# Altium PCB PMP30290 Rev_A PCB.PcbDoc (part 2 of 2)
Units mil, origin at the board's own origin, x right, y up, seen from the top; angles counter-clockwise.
Board outline 2460 x 2050 mil, 4 copper layers (Top Layer, Inner Layer 1, Inner Layer 2, Bottom Layer), stack 84.834 mil thick; 95 components, 59 nets, 283 pads, 121 vias.
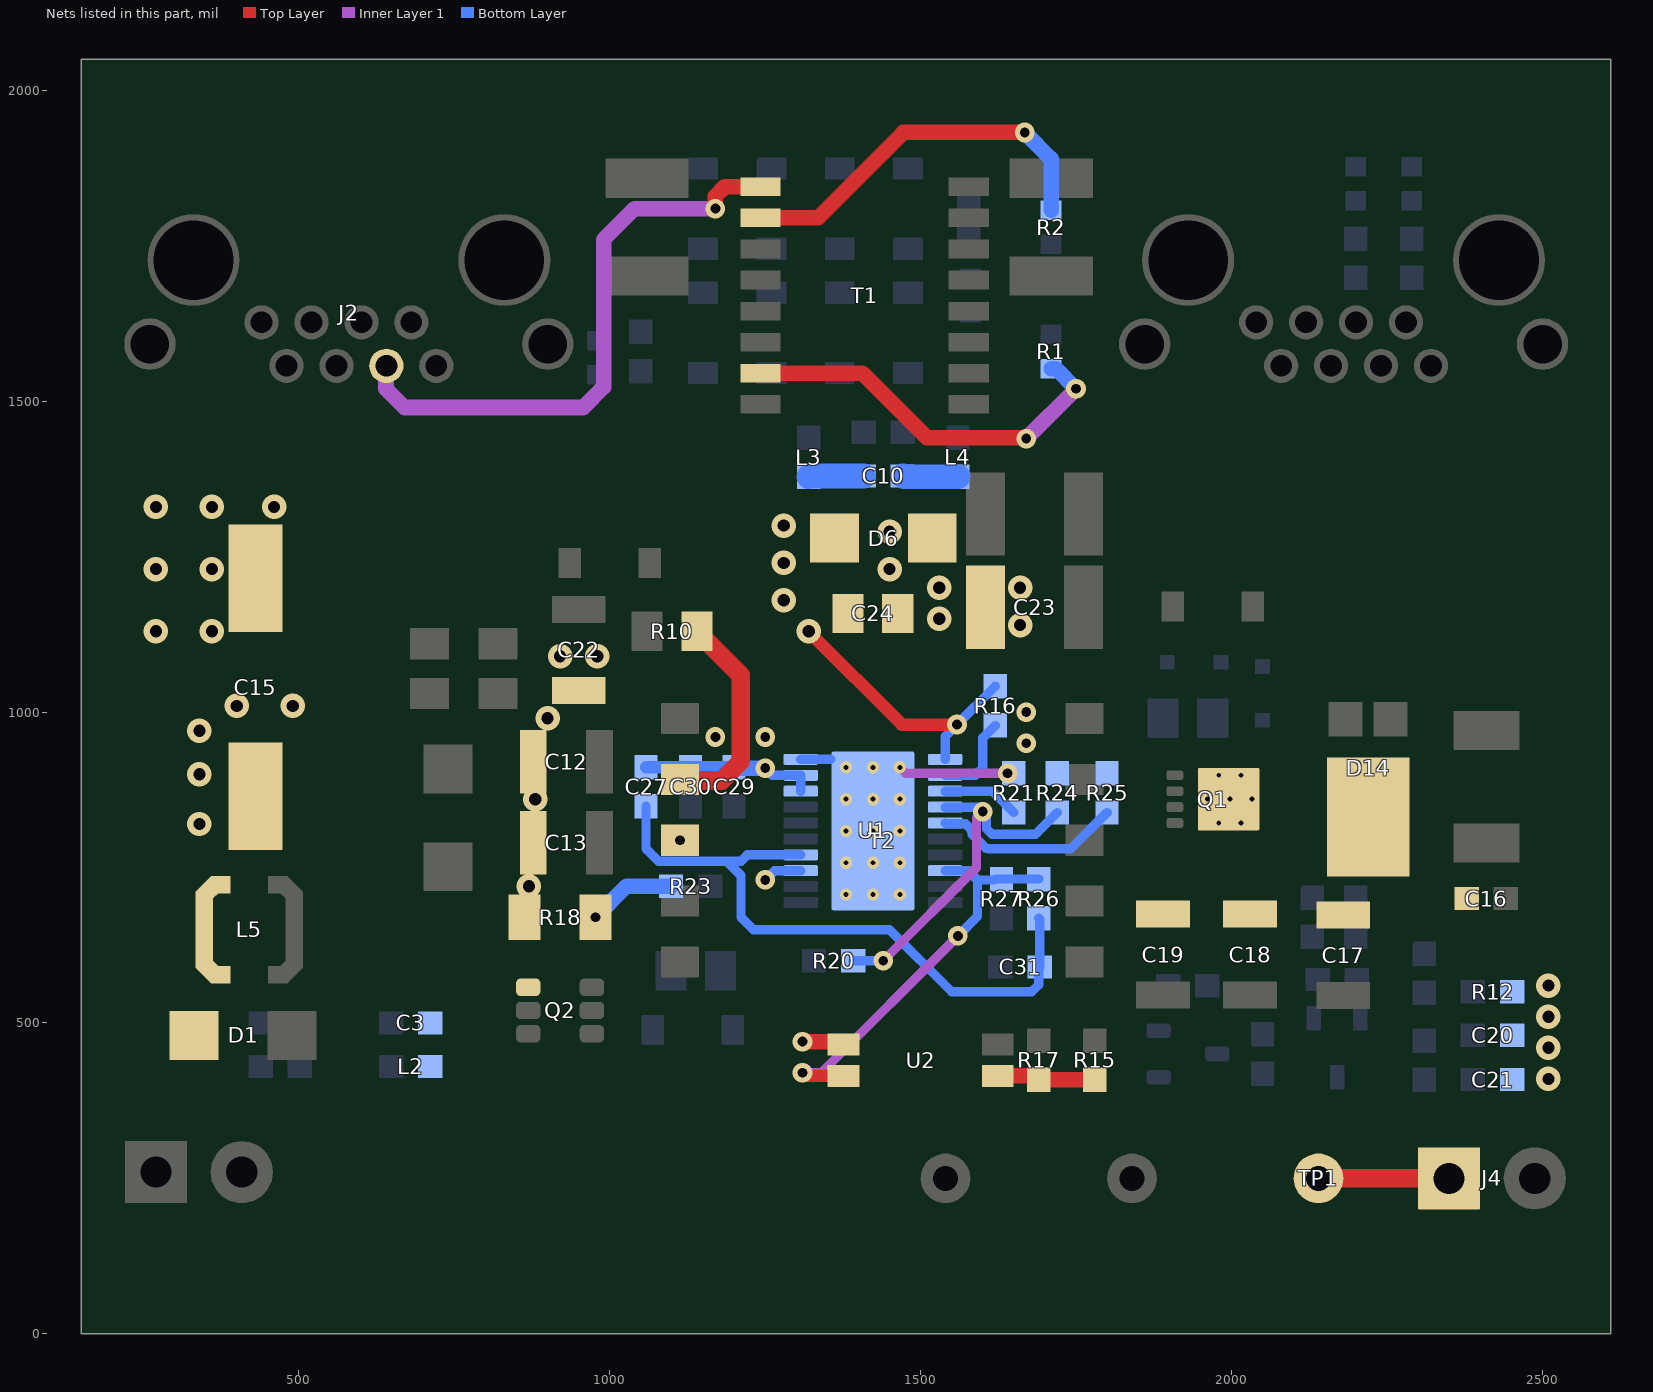
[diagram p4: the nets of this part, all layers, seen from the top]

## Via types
v1: diameter 39.37, hole 19.68, Top Layer to Bottom Layer, 53 vias
v2: diameter 31.5, hole 15.75, Top Layer to Bottom Layer, 46 vias
v3: diameter 19.68, hole 7.87, Top Layer to Bottom Layer, 16 vias
v4: diameter 19.68, hole 7.87, Top Layer to Bottom Layer, tented both sides, 6 vias

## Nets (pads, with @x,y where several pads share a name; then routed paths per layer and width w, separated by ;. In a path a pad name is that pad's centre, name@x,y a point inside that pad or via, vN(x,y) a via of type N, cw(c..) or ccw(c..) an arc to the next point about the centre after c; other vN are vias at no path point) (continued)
NetJ2_6: J2.6 T1.9 | length 949.9
  Top Layer w25: v2(1170,1810) 1170,1830 1185.01,1845.01 T1.9@1242.51,1845.01
  Inner Layer 1 w25: J2.6@640.63,1557.01 640,1556.38 640,1520 670,1490 957.24,1490 990,1522.76 990,1760 1040,1810 v2(1170,1810)
NetQ2_4: Q2.4 R18.2 R23.2 | length 142.1
  Bottom Layer w25: v2(977.09,670) 1027.09,720 R23.2@1098.5,720
NetR1_2: R1.2 T1.15 | length 637.6
  Top Layer w25: T1.15@1242.51,1545.01 1406.49,1545.01 1510,1441.5 1668.5,1441.5 v2(1670,1440)
  Inner Layer 1 w25: v2(1670,1440) v2(1750,1520)
  Bottom Layer w25: R1.2@1710,1552.44 1717.56,1552.44 v2(1750,1520)
NetR2_2: R2.2 T1.10 | length 624.4
  Top Layer w25: T1.10@1242.51,1795.01 1335.01,1795.01 1472.4,1932.4 v2(1667.6,1932.4)
  Bottom Layer w25: v2(1667.6,1932.4) 1710,1890 R2.2@1710,1807.56
NetR10_2: R10.2 T2.4 | length 349.9
  Top Layer w30: T2.4@1112.81,891.82 1114.63,890 1180,890 1210.61,920.61 1210.61,1059.39 R10.2@1140,1130
NetR15_1: R15.1 R17.2 U2.1 | length 158.7
  Top Layer w25: U2.1@1624.02,415 1683.5,415 R17.2@1690,408.5 R15.1@1780,408.5
NetR16_1: R16.1 U1.2 | length 142.2
  Bottom Layer w15: U1.2@1539.45,898.39 1588.39,898.39 1600,910 1600,958.5 R16.1@1620,978.5
NetR20_1: R20.1 R24.2 U1.4 | length 584.1
  Inner Layer 1 w15: v2(1440,600) 1590,750 1590,830 v2(1600,840)
  Bottom Layer w15: R20.1@1391.5,600 v2(1440,600) ; U1.4@1539.45,847.2 1598.72,847.2 1605.93,840 1605.93,812.45 1614.93,803.44 1684.94,803.44 R24.2@1720,838.5
NetR21_2: R21.2 U1.3 | length 124.8
  Bottom Layer w15: U1.3@1539.45,872.8 1615.71,872.8 R21.2@1650,838.5
NetR25_2: R25.2 U1.5 | length 305.8
  Bottom Layer w15: U1.5@1539.45,821.61 1540.81,820.26 1572.23,820.26 1582.38,810.11 1582.38,807.62 1583.05,806.95 1583.05,802.98 1605.46,780.57 1609.43,780.57 1610,780 1741.5,780 R25.2@1800,838.5
NetR26_1: R26.1 R27.1 U1.8 U2.4 | length 669.5
  Top Layer w20: v2(1310,420) 1315,415 U2.4@1375.98,415
  Inner Layer 1 w15: v2(1310,420) 1340,420 v2(1560,640)
  Bottom Layer w15: U1.8@1539.45,744.84 1576.61,744.84 1591.46,730 ; v2(1560,640) 1591.46,671.46 1591.46,730 ; R26.1@1690,731.5 1620,731.5 1618.5,730 1591.46,730
PWRGND: C3.2 C12.2 C13.2 C15.2 C22.2 C23.1 C27.1 C29.2 C30.2 L2.2 R18.1 R24.1 R25.1 T2.3 U1.13 U1.18 U1.19 U2.3 | length 411.2
  Top Layer w25: v2(1310,470) 1370.98,470 U2.3@1375.98,465
  Bottom Layer w15: v2(1250,730) 1264.84,744.84 U1.13@1307.17,744.84 ; v2(1250,910) 1261.61,898.39 U1.19@1307.17,898.39 U1.18@1307.17,872.8
  Bottom Layer w20: C27.1@1058.31,911.5 C30.2@1130,911.5 C29.2@1200,911.5
  Bottom Layer w25: C29.2@1200,911.5 1201.5,910 v2(1250,910)
  other v1: 870,720 880,860 900,990 920,1090 980,1090 270,1130 360,1130 1660,1140 1660,1200 270,1230 360,1230 270,1330 360,1330 460,1330
  other v2: 1112.81,793.82 1670,950 1170,960 1250,960 1670,1000
VB: C27.2 C31.1 R26.2 U1.14 | length 1070.3
  Bottom Layer w15: C27.2@1058.31,848.5 1058.31,780 1078.31,760 1190,760 ; U1.14@1307.17,770.43 1221.56,770.43 1211.12,760 1190,760 ; R26.2@1690,668.5 1691.5,667.01 C31.1@1691.5,590 1690,588.5 1690,561.46 1678.54,550 1550,550 1450,650 1231.12,650 1211.12,670 1211.12,737.06 1190,758.18 1190,760
VDD: C10.1 C15.1 C24.1 D1.1 D6.1 L3.2 L5.1 R16.2 U1.1 | length 540.6
  Top Layer w20: v1(1320,1130) 1470,980 v2(1558.5,980)
  Bottom Layer w15: U1.1@1539.45,923.98 1539.45,960.94 v2(1558.5,980) R16.2@1620,1041.5
  Bottom Layer w40: L3.2@1320,1378.5 1321.5,1380 C10.1@1408.5,1380
  other v1: 340,820 340,900 340,970 400,1010 490,1010 1280,1180 1280,1240 1280,1300
VOUT: C16.2 C17.1 C18.1 C19.1 C20.1 C21.1 D14.3 J4.1 Q1.5 Q1.6 Q1.7 Q1.8 Q1.9@1995.39,860 R12.2 TP1.1 | length 210
  Top Layer w30: TP1.1@2140,250 J4.1@2350,250
  other v1: 2510,410 2510,460 2510,510 2510,560
  other v3: 1979.65,821.61 2015.28,821.61 1961.83,860 1997.46,860 2033.09,860 1979.65,898.39 2015.28,898.39
VSS: C10.2 C24.2 D6.2 L4.2 R21.1 U1.20 U1.21@1423.31,808.82 | length 314.7
  Inner Layer 1 w15: v4(1466.61,911.18) 1476.3,901.5 v2(1640,901.5)
  Bottom Layer w15: U1.20@1307.17,923.98 1355.39,923.98
  Bottom Layer w40: C10.2@1471.5,1380 1472.99,1378.5 L4.2@1560,1378.5
  other v1: 1530,1150 1530,1200 1450,1230 1450,1290
  other v3: 1380,757.64 1423.31,757.64 1466.61,757.64 1380,808.82 1423.31,808.82 1466.61,808.82 1380,860 1423.31,860 1466.61,860
  other v4: 1380,706.46 1423.31,706.46 1466.61,706.46 1380,911.18 1423.31,911.18
pads on no net: J2.4 J2.5 J2.7 J2.8 Q1.9@1961.83,833.92 Q1.9@1961.83,886.08 Q1.9@1982.89,860 Q1.9@1997.46,833.92 Q1.9@1997.46,886.08 Q1.9@2016.26,821.61 Q1.9@2016.26,847.2 Q1.9@2016.26,872.8 Q1.9@2016.26,898.39 T1.4 T1.5 T1.12 T1.13 T2.5 T2.8 T2.9 U1.6 U1.7 U1.9 U1.10 U1.11 U1.12 U1.21@1423.31,808.82

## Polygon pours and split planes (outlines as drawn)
GND on Inner Layer 2 "GND Secundary" (solid, pour order 60): 1630,513.82 1630,360 1630,357.6 1632.4,360 2281.1,360 2281.1,150 2560,150 2560,360 2560,870 2140,870 2050,780 2006.18,780 1740,513.82
PWRGND on Inner Layer 2 "PWR Ground Plane" (solid, pour order 58): 220,1410 1590,1410 1680,1320 1680,1064.98 1818.31,918.06 1818.31,708.31 1700,590 1476.18,590 1400,513.82 1400,390 1370,360 220,360 200,380 200,1390 210,1400
BSP on Inner Layer 2 "BSP" (solid, pour order 0): 2550,1920 210,1920 210,1460 2550,1460
PWRGND on Top Layer "Top Layer-No Net 5" (solid, pour order 72): 220,1350 240,1370 540,1370 540,1070 223.31,1070
PWRGND on Top Layer "Top Layer-No Net 4" (solid, pour order 70): 1580,1230 1678.92,1230 1680,1228.92 1680,1108.83 1581.17,1108.83 1580,1110
GND on Top Layer "GND Secundary Top" (solid, pour order 66): 1730,1385.75 1864.25,1385.75 1865.75,1384.25 1880,1370 1880,1270 1830,1220 1830,1140 1790,1100 1731.89,1100 1730,1101.89
GND on Top Layer "Top Layer-No Net 3" (solid, pour order 56): 1670,731.5 1838.5,731.5 1840,730 1840,630 1850,620 2260,620 2260,405.32 2238.9,384.21 1888.39,384.21 1860,412.6 1860,487.4 1860,490 1830,520 1690,520 1670,540
VSS on Top Layer "Top Layer-No Net 2" (solid, pour order 52): 1360,936.77 1490,936.77 1490,680.87 1360,680.87
NetD11_1 on Top Layer "Bottom Layer-No Net 7" (solid, pour order 50): 2020,1200 2110,1200 2110,1128.75 2021.25,1128.75 2020,1127.5
NetD12_1 on Top Layer "Bottom Layer-No Net 6" (solid, pour order 48): 1840.49,1210 1925.22,1210 1925.22,1130 1840.49,1130
NetD12_1 on Top Layer "Bottom Layer-No Net 6" (solid, pour order 46): 1732.21,1073.82 1796.94,1073.82 1827.79,1073.82 1827.79,1042.97 1827.79,1002.97 1789.48,964.67 1732.21,964.67
NetD13_1 on Top Layer "D13-1" (solid, pour order 40): 1840,1110 2460,1110 2520,1050 2520,970 2520,880 2510,870 2352.91,870 2352.91,874.09 2347.01,880 2347.01,920 2347.01,922.99 2320,950 1920,950 1920,849.03 1912.49,841.52 1711.52,841.52 1710,840 1710,940 1818.31,940 1820,940 1840,960
VOUT on Top Layer "Vout" (solid, pour order 38): 1940,930 2140.5,930 2150,930 2299.72,930 2320,910 2320,730 2410,730 2410,671.46 2550,671.46 2550,150 2418.9,150 2280,150 2280,630 1860,630 1850,640 1850,650 1850,760 1870,780 1920,780 1940,800
VDD on Top Layer "Vdd Top" (solid, pour order 32): 1250,1320 1400,1320 1400,1230 1408.5,1221.5 1410,1221.5 1410,1110 1290,1110 1250,1150 1250,1160
VSS on Top Layer "Vss Top" (solid, pour order 30): 1430,1320 1560.08,1320 1560,1319.92 1560,1150 1520,1110 1430,1110
AUX on Top Layer "Aux" (solid, pour order 20): 450,540 590,540 600,530 600,410 570,380 450,380
NetC11_1 on Top Layer "Bottom Layer-No Net 1" (solid, pour order 16): 630,1400 860,1400 1588.54,1400 1630,1380 1630,1251.89 1580,1251.89 1580,1330 1200,1330 860,1330 860,1070 630,1070
NetC11_1 on Top Layer "Bottom Layer-No Net" (solid, pour order 14): 450,750 560,750 590,720 590,630 590,580 570,560 450,560
NetC14_2 on Top Layer "Top Layer-No Net" (solid, pour order 2): 650,1060 860,1060 860,1000 800,940 800,860 650,860
VDD on Top Layer "Vdd" (solid, pour order 4): 220,380 410,380 410,740 440,770 510,770 580,840 580,1040 220,1040
NetD15_2 on Top Layer "Switch Node" (solid, pour order 6): 650,830 808.9,830 810,828.9 810,550 830,530 1000,530 1040,570 1040,580 1040,630 1050,640 1058.31,640 1160,640 1212.31,587.69 1212.31,543.82 1210,541.51 1210,400 1190,380 1180,380 680,380 650,410 650,420
NetQ2_4 on Top Layer "CS" (solid, pour order 8): 920,716.26 923.74,720 1000,720 1020,700 1020,650 1020,620 970,620 930,580 930,540 840,540 830,550 830,590 850,610 890,610 900,610 906.26,610 920,623.74
PWRGND on Top Layer "PWR-GND" (solid, pour order 10): 880,1110 1005.12,1110 1005.12,1080 1005.12,1074.88 1020,1060 1020,1010 1010,1000 950,1000 940,990 930,980 930,770 910,750 910,644.57 900,634.57 835.43,634.57 830,640 830,950 880,1000
NetC11_1 on Top Layer "Power Plus" (solid, pour order 12): 950,980 960,990 1040,990 1050,980 1050,770 1080,740 1143.03,740 1150,740 1150,656.97 1053.03,656.97 1040,670 1040,710 1040,720 1020,740 950,740 940,750 940,970
GND on Inner Layer 1 "GND Secundary Inner L1" (solid, pour order 64): 1730,1385.75 1865.75,1385.75 1865.75,1384.25 1880,1370 1880,1270 1840,1230 1830,1220 1830,1100 1790,1060 1790,900 1870,820 1870,580 1820,530 1818.31,530 1740,530 1721.02,548.98 1721.02,561.46 1720,562.48 1720,888.7 1720,1385.75
VDD on Inner Layer 1 "Inner Layer 1-No Net" (solid, pour order 34): 220,1350 220,810 260,770 340,770 430,770 540,880 540,1070 540,1180 600,1240 1110,1240 1250,1100 1350,1100 1400,1150 1400,1211.1 1400,1320 1350,1370 240,1370
NetC11_1 on Inner Layer 1 "Top Layer-No Net 1" (solid, pour order 18): 490,750 580,840 580,1150 610,1180 620,1180 860,1180 1058.31,981.69 1058.31,898.7 1058.31,750 1038.31,730 1030,730 1020,720 798.5,720 628.5,550 490,550
PWRGND on Bottom Layer "PWR Ground Plane" (solid, pour order 68): 220,1410 1590,1410 1680,1320 1680,1062.52 1818.31,920 1818.31,708.31 1700,590 1476.18,590 1400,513.82 1400,390 1370,360 220,360 200,380 200,1390 210,1400
GND on Bottom Layer "GND Secundary" (solid, pour order 62): 1625.49,510.9 1625.49,357.08 1625.49,354.68 1627.89,357.08 2276.59,357.08 2276.59,147.08 2555.49,147.08 2555.49,357.08 2555.49,867.08 2135.49,867.08 2045.49,777.08 2001.67,777.08 1735.49,510.9
VOUT on Bottom Layer "Vout Bottom" (solid, pour order 54): 2430,590 2550,590 2550,370 2430,370
NetD12_1 on Bottom Layer "Bottom Layer-No Net 5" (solid, pour order 44): 1840,1200 1910,1200 1910,1130 1920,1120 1920,950 1856,950 1840,1040 1800,1040 1790,1050 1790,1073.82 1800,1090 1840,1090
NetD11_1 on Bottom Layer "Bottom Layer-No Net 4" (solid, pour order 42): 1940,1033.94 2090,1033.94 2090,1120 2060,1120 2051.25,1128.75 2051.25,1200 2130,1200 2130,990 2090,950 1940,950
VDD on Bottom Layer "Vdd Bottom" (solid, pour order 36): 1250,1400 1410,1400 1410,1140 1370,1100 1340,1100 1250,1100 1220,1130 1220,1380
VSS on Bottom Layer "Vss" (solid, pour order 28): 1430,1400 1580,1400 1580,1160 1490,1070 1490,930 1360,930 1360,1070 1430,1140
NetC2_2 on Bottom Layer "Bottom Layer-No Net 3" (solid, pour order 26): 670,458.54 630,458.54 591.46,420 560,420 550,420 530,440 530,450 521.46,458.54 520,458.54 480,458.54 480,401.46 478.54,400 470,400 400,400 350,350 350,320 350,175 476.69,175 476.69,350 484.29,357.6 490,357.6 670,357.6
AUX on Bottom Layer "Bottom Layer-No Net 2" (solid, pour order 24): 670,550 668.9,548.9 480,548.9 480,470 481.46,471.46 531.02,471.46 540,462.48 540,440 550,430 590,430 631.46,471.46 670,471.46
NetC2_1 on Bottom Layer "M2 Board Dimensions-No Net" (solid, pour order 22): 460,548.9 458.9,550 230,550 200,520 200,180 340,180 340,357.6 392.4,410 460,410

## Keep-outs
Keep-Out Layer:
  text ".Layer_Name" at 577,-858.49 h60

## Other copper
Top Layer:
  text ".Layer_Name" at 577,-858.49 h60
Bottom Layer:
  text ".Layer_Name" at 577,-858.49 h60

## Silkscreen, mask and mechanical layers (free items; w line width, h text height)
Top Overlay:
  lines w15: 198.9,357.6 198.9,1932.4 2561.1,1932.4 2561.1,357.6 198.9,357.6
  text "DATA" at 700,2010 h40 r180
  text "ETHERNET POWER" at 2450,2010 h40 r180
  text "AUX" at 190,40 h40
  text "RTN" at 360,40 h40
  text "'.PRJ_Number'.PCB_Rev-" at 1010,40 h108.27
  text "Vout" at 2270,30 h40
  text "GND" at 2450,30 h40
  text ".Layer_Name" at 577,-858.49 h60
Bottom Overlay:
  text ".Layer_Name" at 577,-858.49 h60
Top Paste:
  text ".Layer_Name" at 577,-858.49 h60
Bottom Paste:
  text ".Layer_Name" at 577,-858.49 h60
Top Solder:
  text ".Layer_Name" at 577,-858.49 h60
  text ".Layer_Name" at 577,-858.49 h60
Bottom Solder:
  text ".Layer_Name" at 577,-858.49 h60
Drill Guide:
  text ".Layer_Name" at 577,-858.49 h60
M1 Board Outline:
  the board outline again, w10
  text ".Layer_Name" at 577,-858.49 h60
M2 Board Dimensions:
  rectangle: 125,-400 500,-275
  rectangle: 0,-275 125,-150
  lines w7: 0,-275 1000,-275 ; 0,-150 0,-400 1000,-400 1000,-150 ; 125,-400 125,-150 ; 250,-400 250,-150 ; 500,-400 500,-150 ; 750,-400 750,-150
  text ".Layer_Name" at 577,-858.49 h60
M3 3D STEP Top:
  text ".Layer_Name" at 577,-858.49 h60
M4 3D STEP Bottom:
  text ".Layer_Name" at 577,-858.49 h60
M5 Assembly Top:
  lines w10: -292,-930.17 6308,-930.17 ; -292,-726.83 6310,-726.83 ; -292,-523.5 -292,-1133.5 3713,-1133.5 6310,-1133.5 6310,-523.5 -291.5,-523.5 -291.5,-1133.5 1284,-1133.5 ; 2173,-1133.5 2173,-523.5 ; 3440,-726.83 3440,-523.5 ; 4280,-726.83 4280,-523.5 ; 4902,-1140 4902,-937.17
  lines w15: 198.9,357.6 2561.1,357.6 2561.1,1932.4 198.9,1932.4 198.9,357.6
  text "COMPONENTS MARKED 'DNP' SHOULD NOT BE POPULATED." at 1153.5,-318.5 h60
  text "ASSEMBLY VARIANT:" at 1153,-434 h60
  text ".VariantName" at 2189,-434 h60
  text "PCB VIEWED FROM TOP SIDE" at -228.5,-655.67 h60
  text "BOARD #:" at 2248,-655.67 h60
  text ".PRJ_Number" at 2793.5,-655.67 h60
  text "REV:" at 3638,-655.67 h60
  text ".PCB_Rev" at 3929.5,-655.67 h60
  text "SVN REV:" at 4476,-655.67 h60
  text ".VersionControl_RevNumber" at 4982,-655.67 h60
  text "TID #:" at 2248,-859 h60
  text ".TID" at 2793.5,-859 h60
  text "PLOT NAME =" at -228.5,-1064.34 h60
  text ".plot_File_Name" at 577,-1064.34 h60
  text "GENERATED    :" at 2250,-1064.34 h60
  text ".Print_Date" at 3119.5,-1064.34 h60
  text ".Print_Time" at 3848.5,-1064.34 h60
  text "TEXAS INSTRUMENTS" at 5113,-1064.34 h60
M6 Assembly Bottom:
  lines w10: -292.5,-727.33 6309.5,-727.33 ; -290.5,-930.67 6309.5,-930.67 ; 1115.5,-1140.5 1115.5,-937.67 ; 1737.5,-727.33 1737.5,-524 ; 2577.5,-727.33 2577.5,-524 ; 3844.5,-1134 3844.5,-524 ; 4733.5,-1134 6309,-1134 6309,-524 -292.5,-524 -292.5,-1134 2304.5,-1134 6309.5,-1134 6309.5,-524
  text "COMPONENTS MARKED 'DNP' SHOULD NOT BE POPULATED." at 6102,-318 h60
  text ".VariantName" at 5058,-434 h60
  text "ASSEMBLY VARIANT:" at 6097,-434 h60
  text ".VersionControl_RevNumber" at 1035.5,-656.17 h60
  text "SVN REV:" at 1541.5,-656.17 h60
  text ".PCB_Rev" at 2088,-656.17 h60
  text "REV:" at 2379.5,-656.17 h60
  text ".PRJ_Number" at 3224,-656.17 h60
  text "BOARD #:" at 3769.5,-656.17 h60
  text "PCB VIEWED FROM BOTTOM SIDE" at 6246,-656.17 h60
  text ".TID" at 3224,-859.5 h60
  text "TID #:" at 3769.5,-859.5 h60
  text "TEXAS INSTRUMENTS" at 904.5,-1064.84 h60
  text ".Print_Time" at 2169,-1064.84 h60
  text ".Print_Date" at 2898,-1064.84 h60
  text "GENERATED    :" at 3767.5,-1064.84 h60
  text ".plot_File_Name" at 5440.5,-1064.84 h60
  text "PLOT NAME =" at 6246,-1064.84 h60
M9 Title Sheet:
  drawing of 57 lines, arcs and shapes, not listed
  text "1" at 739.84,8036.5 h70
  text "2" at 3235.5,8036.5 h70
  text "3" at 5724.84,8036.5 h70
  text "4" at 8231.51,8036.5 h70
  text "5" at 10730.5,8036.5 h70
  text "6" at 13235.5,8036.5 h70
  text "A" at -416.5,6893.5 h70
  text "A" at 14383.5,6893.5 h70
  text "B" at -416.5,4513.5 h70
  text "B" at 14383.5,4513.5 h70
  text "C" at -416.5,2138.5 h70
  text "C" at 14383.5,2138.5 h70
  text "PROJECT TITLE:" at 11343.5,277.5 h45
  text ".PRJ_Title" at 11393.5,144.17 h70
  text "DESIGNED FOR:" at 11343.5,-23.5 h45
  text ".PRJ_Customer" at 11393.5,-163.5 h70
  text "D" at -416.5,-231.5 h70
  text "D" at 14383.5,-231.5 h70
  text "FILE NAME:" at 11343.5,-323.5 h45
  text ".PCB_File_Name_No_Path" at 11393.5,-443.5 h70
  text "Texas Instruments (TI) and/or its licensors do not warrant the accuracy or completeness of this specification" at 6374,-605.34 h45
  text "ENGINEER:" at 11343.5,-613.5 h45
  text "LAYOUT BY:" at 12848.5,-613.5 h45
  text "or any information contained therein. TI and/or its licensors do not warrant that this design will meet" at 6329.01,-718 h45
  text ".PRJ_Engineer" at 11393.5,-768.49 h70
  text ".PCB_Layout" at 12899,-768.49 h70
  text "the specifications, will be suitable for your application or fit for any particular purpose, or will operate in" at 6329.01,-830.67 h45
  text ".Layer_Name" at 577,-858.49 h60
  text "ALTIUM DESIGNER VERSION:" at 12848.5,-923.5 h45
  text "an implementation. TI and/or its licensors do not warrant that the design is production worthy. You should" at 6329.01,-943.33 h45
  text "completely validate and test your design implementation to confirm the system functionality for your application." at 6374,-1056 h45
  text ".print_Scale" at 11393.5,-1056.83 h70
  text ".Application_BuildNumber" at 12899,-1056.83 h70
  text "1" at 739.84,-1263.5 h70
  text "2" at 3235.5,-1263.5 h70
  text "3" at 5724.84,-1263.5 h70
  text "4" at 8231.51,-1263.5 h70
  text "5" at 10730.5,-1263.5 h70
  text "6" at 13235.5,-1263.5 h70
M10 Fab Notes:
  drawing of 173 lines, arcs and shapes, not listed
  text "DESIGN INFORMATION" at 12378.02,6201 h60
  text "MIN. TRACK WIDTH:" at 11733.46,6021 h60
  text "8" at 12829.7,6021 h60
  text "MIL" at 12984.46,6021 h60
  text "MIN. CLEARANCE:" at 11733.46,5889 h60
  text "0.2" at 12769.7,5889 h60
  text "mm" at 12984.46,5889 h60
  text "MIN. VIA PAD SIZE:" at 11733.46,5757 h60
  text "24" at 12799.71,5757 h60
  text "MIL" at 12984.46,5757 h60
  text "0.05mm (2MIL)" at 12428.46,5615.29 h60
  text "MINIMUM ANNULAR RING" at 11404.23,5611 h60
  text "EXTERNAL" at 13136.46,5611 h60
  text "PER" at 11604.23,5493 h60
  text "IPC-D-275 CLASS 2 LEVEL C" at 11824.23,5493 h60
  text "MIL, HOLES" at 13312.46,5380.71 h60
  text "+/-" at 12920,5380 h60
  text "+/-" at 13774,5380 h60
  text "REGISTRATION TOLERANCES:" at 11404.23,5375 h60
  text "METAL" at 12604,5375 h60
  text "5" at 13180.2,5375 h60
  text "3" at 14013.2,5375 h60
  text "MIL" at 14129.46,5375 h60
  text "+/-" at 13774,5262 h60
  text "HOLE SIZE TOLERANCE (UNLESS OTHERWISE SPECIFIED):" at 11404.23,5257 h60
  text "3" at 14013.2,5257 h60
  text "MIL" at 14129.46,5257 h60
  text "MATERIAL:" at 11329.46,5047.54 h60
  text "FR-4 High Tg" at 12315.9,4907.21 h60
  text "FR-408" at 11750.46,4898.64 h60
  text "OTHER" at 13238.46,4898.64 h60
  text "X" at 12161,4895 h60
  text "62 MIL (1.6mm) +/-10%" at 12070.56,4735.92 h60
  text "THICKNESS:" at 11404.23,4731.64 h60
  text "X" at 11942.4,4731.64 h60
  text "OTHER" at 13355.46,4731.64 h60
  text "TOLERANCE:" at 11404.23,4573.64 h60
  text "X" at 12243.53,4573.64 h60
  text "ANSI IPC-6012 TYPE 3 CLASS 2" at 12430.48,4573.64 h60
  text "OTHER +/-" at 12430.46,4417.64 h60
  text "BOW & TWIST:" at 11404.23,4260.64 h60
  text "X" at 12243.53,4260.64 h60
  text "ANSI IPC-6012 TYPE 3 CLASS 2" at 12430.48,4260.64 h60
  text "OTHER +/-" at 12430.46,4102.13 h60
  text "DRILLING:" at 11329.46,3963.64 h60
  text "REFERENCE:" at 11404.23,3846.64 h60
  text "X" at 12052.46,3846.64 h60
  text "AS SHOWN" at 12239.46,3846.64 h60
  text "X" at 12953.46,3846.64 h60
  text "NC_DRILL FILES" at 13090.46,3846.64 h60
  text "PTH COPPER THICKNESS:" at 11404.23,3688.64 h60
  text "X" at 12534.46,3688.64 h60
  text "20-30 um" at 12671.46,3688.64 h60
  text "OTHER" at 13388.46,3688.64 h60
  text "BOARD FINISH:" at 11329.46,3529.64 h60
  text "SILKSCREEN:" at 11484.68,3411.64 h60
  text "X" at 12433.46,3411.64 h60
  text "TOP" at 12559.46,3411.64 h60
  text "X" at 12943.46,3411.64 h60
  text "BOTTOM" at 13070.46,3411.64 h60
  text "SILKSCREEN COLOR:" at 11484.68,3244.64 h60
  text "X" at 12432.42,3244.64 h60
  text "WHITE" at 12559.46,3244.64 h60
  text "OTHER" at 13070.46,3244.64 h60
  text "X" at 12563.42,3085.44 h60
  text "GREEN" at 12690.46,3085.44 h60
  text "OTHER" at 13308.46,3085.44 h60
  text "SOLDER RESIST COLOR:" at 11484.68,3074.64 h60
  text "X" at 12563.42,2915.44 h60
  text "MATTE" at 12690.46,2915.44 h60
  text "SEMI-GLOSS" at 13308,2914.8 h60
  text "IMMERSION GOLD (ENIG)" at 12390.46,2726.92 h60
  text "ENEPIG" at 13728,2723.64 h60
  text "SURFACE FINISH:" at 11329.46,2722.64 h60
  text "X" at 12203.51,2722.64 h60
  text "IMM. TIN/SILVER OR EQUIV" at 11659,2565.64 h60
  text "OTHER" at 13090.46,2565.64 h60
  text "ARRAY/PANEL:" at 11329.46,2386.64 h60
  text "CUT AND TRIM PER M1 BOARD OUTLINE" at 12390.46,2382.35 h60
  text "N.C. ROUTE" at 12390.46,2230.64 h60
  text "X" at 13069.46,2230.64 h60
  text "V. SCORE" at 13256.46,2230.64 h60
  text "CERTIFICATION:" at 11329.46,2093.64 h60
  text "MATERIALS AND WORKMANSHIP FOR ALL PCBS" at 12054.46,2093.64 h60
  text "TO MEET OR EXCEED THE REQUIREMENTS OF:" at 12054.46,1995.64 h60
  text "X" at 11680.96,1859.13 h60
  text "ANSI IPC-A-600F CLASS ->" at 11819.96,1859.13 h60
  text "X" at 13459.02,1859.13 h60
  text "2" at 13577.96,1859.14 h60
  text "1" at 13262.96,1857.64 h60
  text "3" at 13931.96,1857.64 h60
  text "X" at 12495.02,1699.64 h60
  text "RoHS" at 12631.96,1699.64 h60
  text "OTHER" at 13276.36,1699.64 h60
  text "PER ORDER" at 13673.42,1699.64 h60
  text "ALL BOARDS MUST MEET OR EXCEED UL94-V0 REQUIREMENTS." at 11357,1534 h60
  text "PCB MUST BEAR THE UL94V-0 UL REGISTERED MATERIAL ID NUMBER" at 11357,1414 h60
  text "ADDITIONAL REQUIREMENTS:" at 11329.46,1240.64 h60
  text "MICROSECTION:" at 11404.23,1125.64 h60
  text "YES" at 12309.96,1125.64 h60
  text "REQUIRED" at 13171.46,969.49 h60
  text "BARE BOARD ELEC. TEST:" at 11404.23,966.64 h60
  text "NONE" at 12709.96,966.64 h60
  text "X" at 13044.46,966.64 h60
  text "PER ORDER" at 13763.46,966.64 h60
  text ".Layer_Name" at 577,-858.49 h60
M11 Gerber Information:
  lines w10: -292,-930.17 6308,-930.17 ; -292,-726.83 6310,-726.83 ; -292,-523.5 -292,-1133.5 3713,-1133.5 6310,-1133.5 6310,-523.5 -291.5,-523.5 -291.5,-1133.5 1284,-1133.5 ; 2173,-1133.5 2173,-523.5 ; 3440,-726.83 3440,-523.5 ; 4280,-726.83 4280,-523.5 ; 4902,-1140 4902,-937.17
  text "ALL ARTWORK VIEWED FROM TOP SIDE" at -228.5,-655.67 h60
  text "BOARD #:" at 2248,-655.67 h60
  text ".PRJ_Number" at 2793.5,-655.67 h60
  text "REV:" at 3638,-655.67 h60
  text ".PCB_Rev" at 3929.5,-655.67 h60
  text "SVN REV:" at 4476,-655.67 h60
  text ".VersionControl_RevNumber" at 4982,-655.67 h60
  text "LAYER NAME =" at -228.5,-858.49 h60
  text "TID #:" at 2248,-859 h60
  text ".TID" at 2793.5,-859 h60
  text "PLOT NAME =" at -228.5,-1064.34 h60
  text ".plot_File_Name" at 577,-1064.34 h60
  text "GENERATED    :" at 2250,-1064.34 h60
  text ".Print_Date" at 3119.5,-1064.34 h60
  text ".Print_Time" at 3848.5,-1064.34 h60
  text "TEXAS INSTRUMENTS" at 5113,-1064.34 h60
M12 Stackup:
  drawing of 191 lines, arcs and shapes, not listed
  text "Layer" at 9790.34,7830 h60
  text "Name" at 10200.26,7830 h60
  text "Material" at 11130,7830 h60
  text "Thickness" at 11989.77,7830 h60
  text "Constant" at 12639.6,7830 h60
  text "Board Layer Stack" at 13209.46,7830 h60
  text "1" at 9790.34,7710 h60
  text "Top Overlay" at 10200.26,7710 h60
  text "2" at 9790.34,7590 h60
  text "Top Solder" at 10200.26,7590 h60
  text "Solder Resist" at 11130,7590 h60
  text "0.40mil" at 11989.77,7590 h60
  text "3.5" at 12639.6,7590 h60
  text "3" at 9790.34,7470 h60
  text "Top Layer" at 10200.26,7470 h60
  text "Copper" at 11130,7470 h60
  text "1.40mil" at 11989.77,7470 h60
  text "4" at 9790.34,7350 h60
  text "Dielectric1" at 10200.26,7350 h60
  text "FR-4" at 11130,7350 h60
  text "59.20mil" at 11989.77,7350 h60
  text "4.8" at 12639.6,7350 h60
  text "5" at 9790.34,7230 h60
  text "Bottom Layer" at 10200.26,7230 h60
  text "Copper" at 11130,7230 h60
  text "1.40mil" at 11989.77,7230 h60
  text "6" at 9790.34,7110 h60
  text "Bottom Solder" at 10200.26,7110 h60
  text "Solder Resist" at 11130,7110 h60
  text "0.40mil" at 11989.77,7110 h60
  text "3.5" at 12639.6,7110 h60
  text "7" at 9790.34,6990 h60
  text "Bottom Overlay" at 10200.26,6990 h60
  text ".Layer_Name" at 577,-858.49 h60
M13 Component Bodies Top:
  text ".Layer_Name" at 577,-858.49 h60
M14 Component Bodies Bottom:
  text ".Layer_Name" at 577,-858.49 h60
M15 Courtyards Top:
  text ".Layer_Name" at 577,-858.49 h60
M16 Courtyards Bottom:
  text ".Layer_Name" at 577,-858.49 h60
Drill Drawing:
  lines w10: 5336.14,2367.21 5363.8,2381.04 5391.46,2367.21 5377.63,2394.87 5391.46,2422.52 5363.8,2408.7 5336.14,2422.52 5349.97,2394.87 5336.14,2367.21 ; 5336.14,2505.5 5349.97,2505.5 5363.8,2491.67 5377.63,2505.5 5391.46,2505.5 5377.63,2519.33 5391.46,2533.15 5377.63,2533.15 5363.8,2546.98 5349.97,2533.15 5336.14,2533.15 5349.97,2519.33 5336.14,2505.5 ; 5336.14,2671.44 5391.46,2671.44 5363.8,2616.13 5336.14,2671.44 ; 5336.14,2740.59 5391.46,2740.59 5391.46,2795.9 5336.14,2795.9 5336.14,2740.59 ; 5336.14,2878.87 5349.97,2878.87 5349.97,2865.04 5377.63,2865.04 5377.63,2878.87 5391.46,2878.87 5391.46,2906.53 5377.63,2906.53 5377.63,2920.36 5349.97,2920.36 5349.97,2906.53 5336.14,2906.53 5336.14,2878.87 ; 5336.14,2989.5 5391.46,2989.5 5391.46,3044.82 5336.14,3044.82 5336.14,2989.5 ; 5336.14,3141.62 5363.8,3113.96 5391.46,3141.62 5363.8,3169.28 5336.14,3141.62 ; 5336.14,3238.42 5336.14,3252.25 5349.97,3266.08 5336.14,3279.91 5336.14,3293.74 5349.97,3293.74 5363.8,3279.91 5377.63,3293.74 5391.46,3293.74 5391.46,3279.91 5377.63,3266.08 5391.46,3252.25 5391.46,3238.42 5377.63,3238.42 5363.8,3252.25 5349.97,3238.42 5336.14,3238.42 ; 5347.21,3000.57 5380.39,3000.57 5380.39,3033.75 5347.21,3033.75 5347.21,3000.57
  lines w12: 5286,2329.87 8518.76,2329.87 ; 5286,3325.54 8518.76,3325.54 ; 5624.17,2205.41 5624.17,3450 ; 5956.28,2205.41 5956.28,3450 ; 6593.29,2205.41 6593.29,3450 ; 6852.64,2205.41 6852.64,3450 ; 7228.06,2205.41 7228.06,3450 ; 7951.91,2205.41 7951.91,3450 ; 5286,2205.41 8518.76,2205.41 8518.76,3450 5286,3450 5286,2205.41
  text "Symbol" at 5360.68,3362.88 h72
  text "Quantity" at 5661.51,3362.88 h72
  text "Finished Hole Size" at 5993.62,3362.88 h72
  text "Plated" at 6630.62,3362.88 h72
  text "Hole Type" at 6889.98,3362.88 h72
  text "Drill Layer Pair" at 7265.4,3362.88 h72
  text "Hole Tolerance" at 7989.25,3362.88 h72
  text "22" at 5661.51,3238.42 h60
  text "7.87mil (0.200mm)" at 5993.62,3238.42 h60
  text "PTH" at 6630.62,3238.42 h60
  text "Round" at 6889.98,3238.42 h60
  text "Top Layer - Bottom Layer" at 7265.4,3238.42 h60
  text "46" at 5661.51,3113.96 h60
  text "15.75mil (0.400mm)" at 5993.62,3113.96 h60
  text "PTH" at 6630.62,3113.96 h60
  text "Round" at 6889.98,3113.96 h60
  text "Top Layer - Bottom Layer" at 7265.4,3113.96 h60
  text "53" at 5661.51,2989.5 h60
  text "19.69mil (0.500mm)" at 5993.62,2989.5 h60
  text "PTH" at 6630.62,2989.5 h60
  text "Round" at 6889.98,2989.5 h60
  text "Top Layer - Bottom Layer" at 7265.4,2989.5 h60
  text "16" at 5661.51,2865.04 h60
  text "35.04mil (0.890mm)" at 5993.62,2865.04 h60
  text "PTH" at 6630.62,2865.04 h60
  text "Round" at 6889.98,2865.04 h60
  text "Top Layer - Bottom Layer" at 7265.4,2865.04 h60
  text "3" at 5661.51,2740.59 h60
  text "40.00mil (1.016mm)" at 5993.62,2740.59 h60
  text "PTH" at 6630.62,2740.59 h60
  text "Round" at 6889.98,2740.59 h60
  text "Top Layer - Bottom Layer" at 7265.4,2740.59 h60
  text "4" at 5661.51,2616.13 h60
  text "50.00mil (1.270mm)" at 5993.62,2616.13 h60
  text "PTH" at 6630.62,2616.13 h60
  text "Round" at 6889.98,2616.13 h60
  text "Top Layer - Bottom Layer" at 7265.4,2616.13 h60
  text "4" at 5661.51,2491.67 h60
  text "61.81mil (1.570mm)" at 5993.62,2491.67 h60
  text "PTH" at 6630.62,2491.67 h60
  text "Round" at 6889.98,2491.67 h60
  text "Top Layer - Bottom Layer" at 7265.4,2491.67 h60
  text "4" at 5661.51,2367.21 h60
  text "128.00mil (3.251mm)" at 5993.62,2367.21 h60
  text "PTH" at 6630.62,2367.21 h60
  text "Round" at 6889.98,2367.21 h60
  text "Top Layer - Bottom Layer" at 7265.4,2367.21 h60
  text "152 Total" at 5661.51,2242.75 h60
  text ".Layer_Name" at 577,-858.49 h60
M17 Embedded Cavity:
  text ".Layer_Name" at 577,-858.49 h60
M18 Embedded Assembly:
  text ".Layer_Name" at 577,-858.49 h60
M19 Embedded Keepout:
  text ".Layer_Name" at 577,-858.49 h60

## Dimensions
198.9,357.6 to 2561.1,357.6 on M2 Board Dimensions
198.9,357.6 to 198.9,1932.4 on M2 Board Dimensions
0,-400 to 1000,-400 on M2 Board Dimensions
